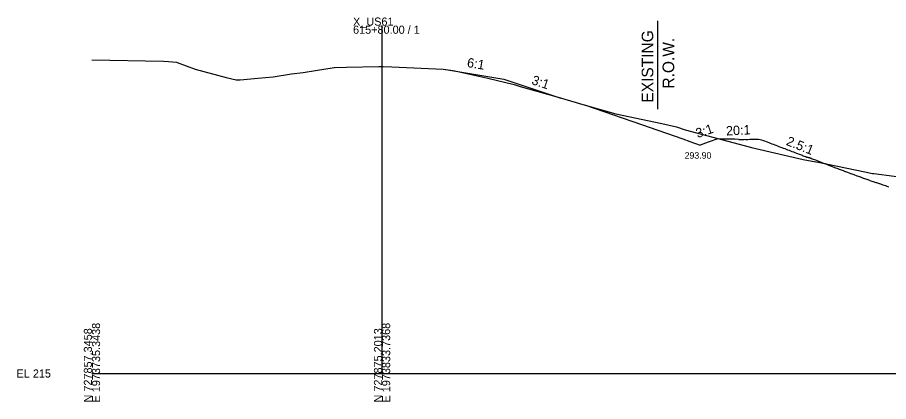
# Model space of a CAD drawing. Extents: x -26 to 1604, y -13 to 9623.
# Drawn here: x -25.7 to 274.6, y 9490.3 to 9622.8 of the extents above; entities that cross this region are included whole.
import ezdxf

# ---------------------------------------------------------------- set-up
doc = ezdxf.new("R2010")
doc.units = 0
for name, color, linetype in [('Default', 7, 'Continuous'), ('Draft_XS_Grid', 7, 'Continuous'), ('DTM CONTOURS_MAJOR', 7, 'Continuous'), ('DTM_X_GROUND', 7, 'Continuous'), ('SLOPE_STAKES_FILL', 7, 'Continuous'), ('XS_CELL', 7, 'Continuous'), ('XS_P_GROUND', 7, 'Continuous'), ('XS_P_TX_DCH', 7, 'Continuous'), ('XS_P_TX_FS_BS', 7, 'Continuous'), ('XS_X_ROW', 7, 'Continuous')]:
    doc.layers.add(name, color=color, linetype=linetype)

msp = doc.modelspace()

# ---------------------------------------------------------------- linework, layer by layer
at = {"layer": 'DTM_X_GROUND'}
msp.add_lwpolyline([(0, 9608.17), (24.71, 9607.69), (26.39, 9607.65), (27.75, 9607.53), (29.16, 9607.41), (29.4, 9607.31), (35.57, 9605.01), (46.27, 9602.11), (49.68, 9601.25), (51.06, 9601.27), (57.19, 9601.91), (62.44, 9602.37), (68.75, 9603.33), (72.76, 9603.84), (77.02, 9604.51), (83.47, 9605.55), (83.57, 9605.56), (87.79, 9605.72), (98.91, 9605.93), (100.44, 9605.96), (103.39, 9605.83), (121.06, 9605.04), (123.58, 9604.68), (125.13, 9604.46), (136.51, 9601.83), (145.57, 9599.74), (147.59, 9599.02), (159.93, 9595.53), (170.05, 9592.55), (180.54, 9589.6), (196.48, 9586.25), (201.51, 9585.06), (204.54, 9584.11), (226.51, 9578.22), (227.81, 9577.85), (228.86, 9577.61), (245.15, 9573.87), (249.56, 9572.98), (250.32, 9572.85), (266.37, 9569.54), (269.11, 9568.99), (269.48, 9568.96), (290.57, 9566.21)], dxfattribs=at)
at = {"layer": 'XS_CELL'}
for p, q in [((100, 9500), (100, 9620)), ((0, 9500), (100, 9500)), ((100, 9500), (600, 9500))]:
    msp.add_line(p, q, dxfattribs=at)
at = {"layer": 'XS_P_GROUND'}
for points in [[(122, 9604.9), (142, 9601.57)], [(142, 9601.57), (161.64, 9595.02)], [(170.12, 9592.54), (189.48, 9585.86), (203.64, 9580.9), (206.08, 9580.05), (209.7, 9578.8)], [(223.03, 9580.75), (221.66, 9580.79), (217.71, 9580.84), (215.92, 9580.9), (215.71, 9580.9), (212.42, 9579.76), (209.7, 9578.8)], [(223.03, 9580.72), (223.69, 9580.76), (223.77, 9580.74), (224.67, 9580.78), (224.77, 9580.76), (225.37, 9580.79), (225.44, 9580.77)], [(225.44, 9580.77), (225.56, 9580.77), (225.77, 9580.78), (226.14, 9580.77), (226.77, 9580.8), (227.15, 9580.79), (227.78, 9580.82), (228.16, 9580.81), (228.78, 9580.84), (229.17, 9580.83), (229.78, 9580.86), (230.39, 9580.73), (230.78, 9580.64), (231.38, 9580.4), (231.78, 9580.26), (232.38, 9580.02), (232.79, 9579.88), (233.37, 9579.64), (233.79, 9579.49), (234.36, 9579.26), (234.79, 9579.11), (235.35, 9578.89), (235.79, 9578.73), (236.34, 9578.51), (236.79, 9578.35), (237.33, 9578.13), (237.8, 9577.96), (238.32, 9577.75), (238.8, 9577.58), (239.31, 9577.38), (239.8, 9577.2), (240.29, 9577), (240.8, 9576.82), (241.28, 9576.63), (241.8, 9576.43), (242.26, 9576.25), (242.81, 9576.05), (243.25, 9575.88), (243.81, 9575.67), (244.23, 9575.5), (244.81, 9575.29), (245.21, 9575.13), (245.81, 9574.91), (246.03, 9574.82), (246.44, 9574.68), (246.55, 9574.65), (246.66, 9574.63), (246.77, 9574.6), (246.89, 9574.57), (247, 9574.55), (247.11, 9574.52), (247.23, 9574.5), (247.34, 9574.47), (247.46, 9574.44), (247.58, 9574.42), (247.69, 9574.39), (247.7, 9574.34), (247.9, 9574.26), (248.28, 9574.11), (248.61, 9573.98), (249.38, 9573.68), (249.68, 9573.56), (250.49, 9573.25), (250.75, 9573.15), (251.6, 9572.82), (251.81, 9572.73), (252.7, 9572.39), (252.87, 9572.32), (253.81, 9571.96), (253.93, 9571.92), (254.92, 9571.54), (254.98, 9571.51), (255.99, 9571.12), (256.02, 9571.11), (256.02, 9571.11), (257.13, 9570.68), (257.13, 9570.68), (257.18, 9570.66), (257.18, 9570.66), (257.18, 9570.66), (257.26, 9570.63), (258.24, 9570.26), (258.95, 9569.98), (259.14, 9569.92), (259.34, 9569.84), (260.41, 9569.44), (260.45, 9569.42), (261.5, 9569.03), (261.56, 9569.01), (262.6, 9568.62), (262.66, 9568.61), (263.69, 9568.22), (263.77, 9568.2), (264.79, 9567.83), (264.88, 9567.8), (265.88, 9567.43), (265.98, 9567.41), (266.98, 9567.05), (267.09, 9567.01), (268.07, 9566.66), (268.2, 9566.63), (269.16, 9566.28), (269.3, 9566.24), (270.26, 9565.9), (270.41, 9565.86), (271.35, 9565.53), (271.52, 9565.49), (272.44, 9565.16), (272.62, 9565.11), (273.54, 9564.8), (273.73, 9564.74), (274.63, 9564.44)]]:
    msp.add_lwpolyline(points, dxfattribs=at)
at = {"layer": 'XS_X_ROW'}
msp.add_line((195, 9621.7), (195, 9591.15), dxfattribs=at)

# ---------------------------------------------------------------- texts
at = {"layer": 'Default'}
for p in [(141.96, 9601.51), (209.36, 9578.84)]:
    msp.add_text('X', height=0.12, dxfattribs=at).set_placement(p)
at = {"layer": 'Draft_XS_Grid'}
msp.add_text('-', height=0.0001, dxfattribs=at).set_placement((0, 9500))
at = {"layer": 'DTM CONTOURS_MAJOR'}
for p in [(203.6, 9580.84), (215.67, 9580.84), (209.96, 9578.84), (209.96, 9578.84)]:
    msp.add_text('X', height=0.12, dxfattribs=at).set_placement(p)
at = {"layer": 'SLOPE_STAKES_FILL'}
msp.add_text('X', height=0.12, dxfattribs=at).set_placement((141.96, 9601.51))
at = {"layer": 'XS_CELL'}
for s, p in [('X_US61', (90, 9620)), ('615+80.00 / 1', (90, 9617.2)), ('EL 215', (-26, 9498.6))]:
    msp.add_text(s, height=2.8, dxfattribs=at).set_placement(p)
for s, p in [('E 1973735.3438', (2.8, 9490)), ('E 1973833.7368', (102.8, 9490)), ('N 727857.3458', (0, 9490)), ('N 727875.2013', (100, 9490))]:
    msp.add_text(s, height=2.8, rotation=90, dxfattribs=at).set_placement(p)
at = {"layer": 'XS_P_GROUND'}
for p in [(121.96, 9604.84), (161.6, 9594.96)]:
    msp.add_text('X', height=0.12, dxfattribs=at).set_placement(p)
at = {"layer": 'XS_P_TX_DCH'}
msp.add_text('293.90', height=2.25, dxfattribs=at).set_placement((204.31, 9574.1))
at = {"layer": 'XS_P_TX_FS_BS'}
for s, rotation, p in [('6:1', 350.5377, (129.12, 9605.76)), ('3:1', 341.5651, (151.3, 9599.89)), ('3:1', 18.4349, (208.76, 9581.21)), ('20:1', 2.8624, (218.65, 9582.08)), ('2.5:1', 338.1986, (239.06, 9578.92))]:
    msp.add_text(s, height=3.24, rotation=rotation, dxfattribs=at).set_placement(p)
at = {"layer": 'XS_X_ROW'}
for s, p in [('EXISTING', (193.5, 9593.45)), ('R.O.W.', (200.7, 9598.29))]:
    msp.add_text(s, height=4, rotation=90, dxfattribs=at).set_placement(p)

doc.saveas('drawing.dxf')
